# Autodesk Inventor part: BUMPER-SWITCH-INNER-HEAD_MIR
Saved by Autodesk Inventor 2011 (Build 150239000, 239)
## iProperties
Created: 2007-08
Part Number: BUMPER-SWITCH-INNER-HEAD_MIR
Document SubType Name: Modeling
Density: 1 g/cm^3
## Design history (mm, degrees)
derived "BUMPER-SWITCH-INNER-HEAD.ipt"
body "Solid1"
tag "TaggingFeature2"
feature "DerivedBody::BUMPER-SWITCH-INNER-HEAD.ipt" dims "d0" = 10
